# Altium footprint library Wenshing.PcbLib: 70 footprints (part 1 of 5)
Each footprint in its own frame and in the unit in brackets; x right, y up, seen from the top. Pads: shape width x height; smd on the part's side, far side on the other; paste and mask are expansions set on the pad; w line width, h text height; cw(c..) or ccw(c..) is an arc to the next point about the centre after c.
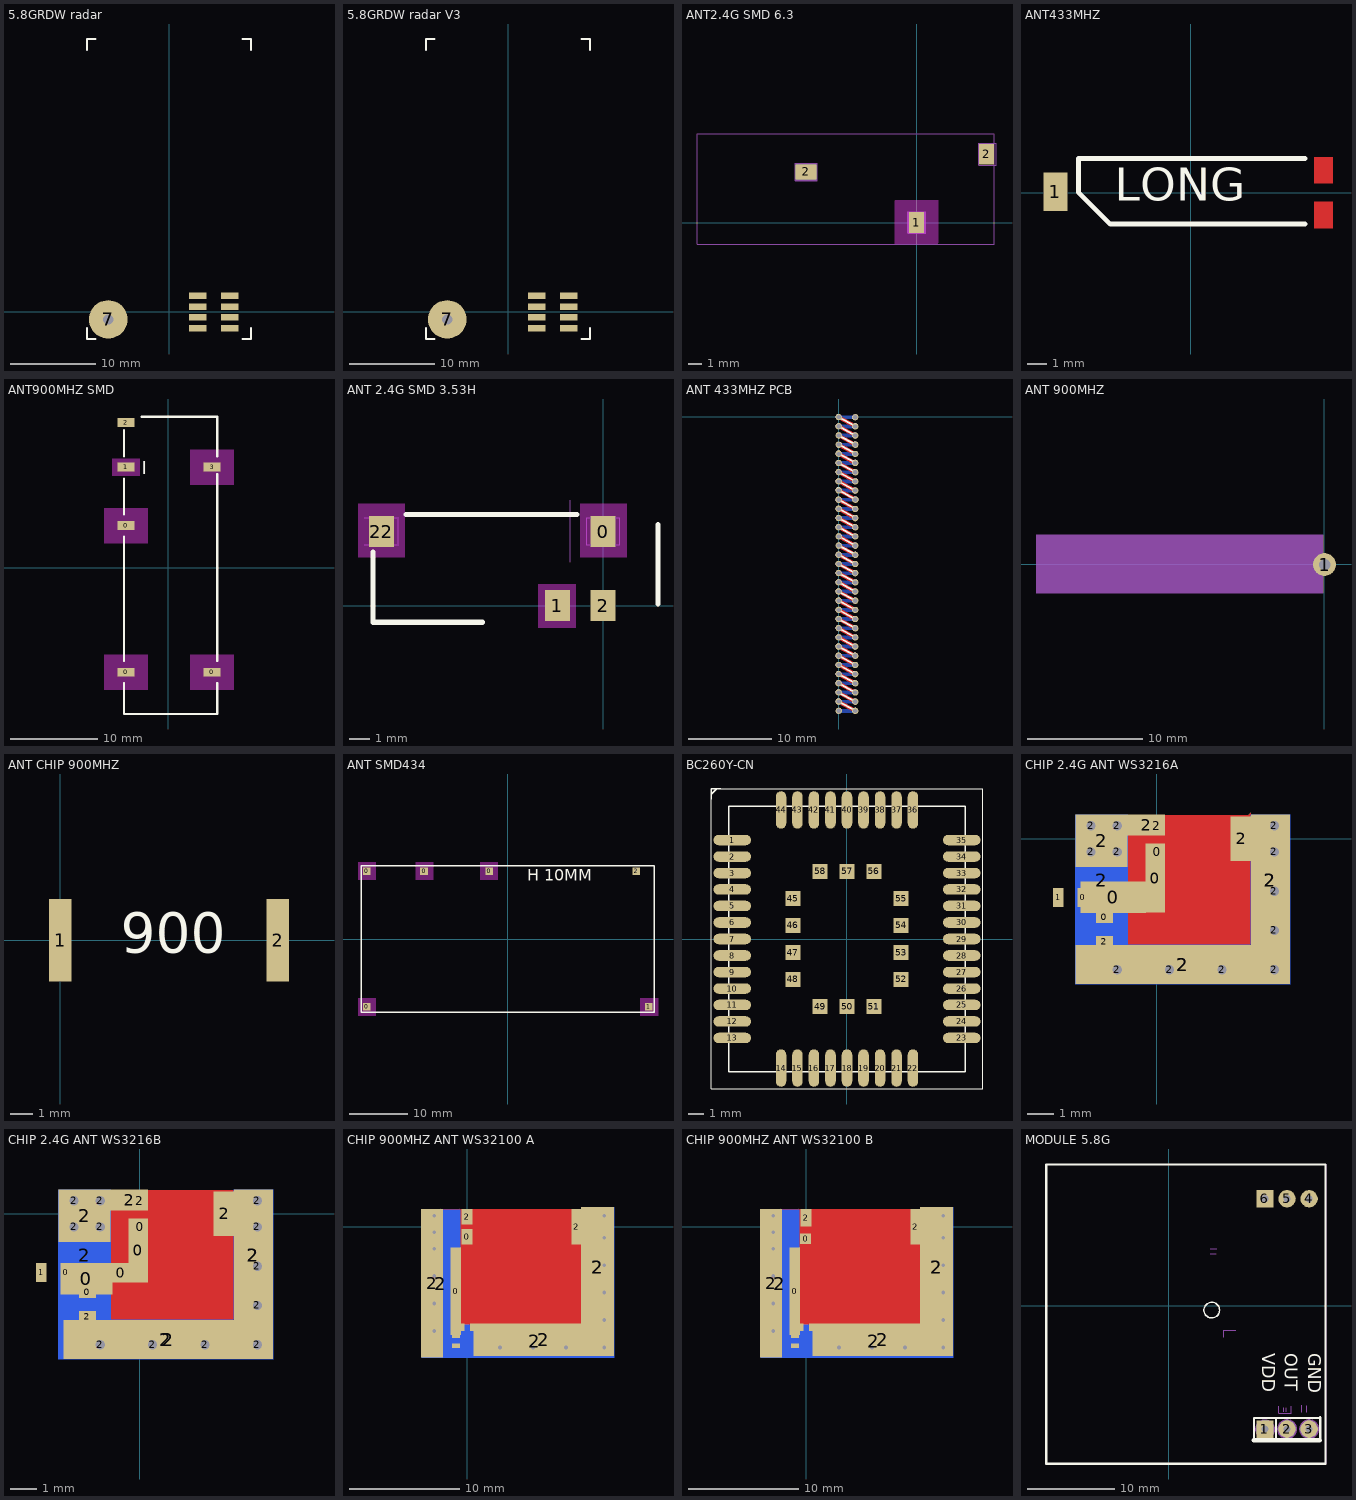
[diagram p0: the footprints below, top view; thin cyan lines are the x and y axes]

## 5.8GRDW radar [mm] "radar 5.8G"
pads (9):
  rect 2.05x0.76 smd: 1(7.109,1.905) 2(3.359,1.905) 3(7.109,0.635) 4(3.359,0.635) 5(7.109,-0.635) 6(3.359,-0.635) 7(7.109,-1.905) 8(3.359,-1.905)
  round 4.5 / inner round 4.5 / far side round 2 hole 1.2: 7(-7.109,-0.871)
Top Layer:
  lines w0.305: -8.587,0.607 ccw(c-7.109,0.607) -7.109,-0.871
Top Overlay:
  lines w0.254: -9.591,-1.887 -9.591,-3.157 -8.575,-3.157 ; -9.591,30.625 -9.591,31.895 -8.575,31.895 ; 8.57,-3.157 9.586,-3.157 9.586,-1.887 ; 8.57,31.895 9.586,31.895 9.586,30.625
Bottom Overlay:
  circle w0.305: c-7.109,-0.871 r2.032
3D body "實驗電源 .step": height 21.53, standoff -21.97, extent -30.585,-22.979 29.921,19.48
3D body: height 3, standoff 0, extent -8.759,-2.521 -5.459,0.779

## 5.8GRDW radar V3 [mm] "radar 5.8G"
pads (9):
  rect 2.05x0.76 smd: 1(7.109,1.905) 2(3.359,1.905) 3(7.109,0.635) 4(3.359,0.635) 5(7.109,-0.635) 6(3.359,-0.635) 7(7.109,-1.905) 8(3.359,-1.905)
  round 4.5 / inner round 4.5 / far side round 2 hole 1.2: 7(-7.109,-0.871)
Top Layer:
  lines w0.305: -8.587,0.607 ccw(c-7.109,0.607) -7.109,-0.871
Top Overlay:
  lines w0.254: -9.591,-1.887 -9.591,-3.157 -8.575,-3.157 ; -9.591,30.625 -9.591,31.895 -8.575,31.895 ; 8.57,-3.157 9.586,-3.157 9.586,-1.887 ; 8.57,31.895 9.586,31.895 9.586,30.625
Bottom Overlay:
  circle w0.305: c-7.109,-0.871 r2.032
3D body "TRW-RADAR 5.8G RT v3.step": height -1.8, standoff -5.66, extent -9.852,-3.195 9.754,33.421
3D body: height 3, standoff 0, extent -8.759,-2.521 -5.459,0.779

## ANT2.4G SMD 6.3 [mil] "ANT 2.4GHZ 6.3X21.8mm"
pads (3):
  rect 43.31x60 smd: 1(-1,0) 2(201,197)
  rect 60x43.31 smd: 2(-320,146)
Keep-Out Layer:
  region: -64,63 -63,64 62,64 62,-58 58,-62 -64,-62
Mechanical 1:
  region: -288.22,120.29 -351.22,120.29 -351.22,171.47 -288.22,171.47
  region: 24.77,-31.28 -26.41,-31.28 -26.41,31.71 24.77,31.71
  lines w0.39: -634.68,-50.97 -634.68,161.63 ; -622.87,-62.78 -193.74,-62.78 ; -59.88,-62.78 58.23,-62.78 ; 196.03,224.62 211.78,224.62 ; 223.59,-11.6 223.59,173.44 223.59,212.81 ; -634.68,-62.78 -634.68,256.12 223.59,256.12 223.59,-62.78 -634.68,-62.78 ; -351.22,120.29 -288.22,120.29 -288.22,171.47 -351.22,171.47 -351.22,120.29 ; -26.41,-31.28 24.77,-31.28 24.77,31.71 -26.41,31.71 -26.41,-31.28 ; 178.31,165.57 229.49,165.57 229.49,228.56 178.31,228.56 178.31,165.57
  text "GND" at -426.17,153.85 h19.68
  text "GND" at 105.59,204.89 h19.68
  text "RF FEED" at 44.35,8.12 h19.68
Mechanical 3:
  lines w0.39: -351.22,138.01 -351.22,153.76 ; -8.7,31.71 7.05,31.71

## ANT433MHZ [mil] "400MHZ -900MHZ   通用"
height 23.62
pads (1):
  rect 50x80 smd: 1(-280,2)
Top Layer:
  rectangle: 254.92,18.48 294.29,73.6
  rectangle: 254.92,-73.69 294.29,-18.57
Top Overlay:
  lines w10: 236.22,-64.96 135.58,-64.96 -65.7,-64.96 -166.34,-64.96 -232.28,0.98 -232.28,70.87 236.22,70.87
  text "LONG" at -157.48,-39.37 h118.11
Top Solder:
  rectangle: 250.98,-78.61 300.2,-14.64
  rectangle: 250.98,14.54 299.21,78.52
  rectangle: -225,-85 220,100
3D body: height 7.87, standoff 0, extent 148.5,-62 224.43,55.68
3D body: height 7.87, standoff 0, extent 90.5,-59 166.43,58.68
3D body: height 7.87, standoff 0, extent 31.5,-60 107.43,57.68
3D body: height 7.87, standoff 0, extent -28.5,-58 47.43,59.68
3D body: height 7.87, standoff 0, extent -73.5,-58 2.43,59.68
3D body: height 7.87, standoff 0, extent -148.5,-56 -72.57,61.68
3D body: height 7.87, standoff 0, extent -206.5,-58 -130.57,59.68
3D body: height 7.87, standoff 0, extent -262.5,-58 -186.57,59.68
3D body: height 51.18, standoff 47.24, extent -201.22,-58 -157,60.93
3D body: height 51.18, standoff 47.24, extent 209,-59.06 253.22,59.88
3D body: height 51.18, standoff 47.24, extent 149.95,-59.06 194.17,59.88
3D body: height 51.18, standoff 47.24, extent 90.89,-59.06 135.11,59.88
3D body: height 51.18, standoff 47.24, extent 31.84,-59.06 76.06,59.88
3D body: height 51.18, standoff 47.24, extent -27.22,-59.06 17,59.88
3D body: height 51.18, standoff 47.24, extent -86.27,-59.06 -42.06,59.88
3D body: height 51.18, standoff 47.24, extent -145.33,-59.06 -101.11,59.88
3D body: height 51.18, standoff 47.24, extent -201.22,-58 -157,60.93
3D body: height 51.18, standoff 0, extent 256,-58 297,60
3D body: height 51.18, standoff 0, extent -288,-58 -247,60
3D body: height 47.24, standoff 0, extent -246,-58.07 255,60.04

## ANT900MHZ SMD [mm]
height 0.6
pads (6):
  rect 1.95x1 smd: 0(-4.855,-12) 0(-4.855,4.8) 0(4.985,-12) 1(-4.855,11.5) 2(-4.855,16.6) 3(5.005,11.5)
Top Overlay:
  lines w0.254: -5.08,-13.208 -5.08,-16.764 5.588,-16.764 5.588,-13.208 ; -5.08,-10.668 -5.08,3.556 ; -5.08,6.096 -5.08,10.16 ; -5.08,12.7 -5.08,15.748 ; -3.048,17.272 5.588,17.272 5.588,12.7 ; 5.588,-10.668 5.588,10.668
  text "I" at -3.048,10.668 h1.52
Keep-Out Layer:
  pour cut-out: -2.35,2.775 -2.35,6.775 -7.35,6.775 -7.35,2.775
  pour cut-out: -3.275,10.525 -3.275,12.475 -6.4,12.475 -6.4,10.525
  pour cut-out: 7.5,-14 7.5,-10 2.5,-10 2.5,-14
  pour cut-out: -2.35,-13.975 -2.35,-9.975 -7.35,-9.975 -7.35,-13.975
  pour cut-out: 7.5,9.5 7.5,13.5 2.5,13.5 2.5,9.5
3D body "ANT 900MHZ ON PCBA (2).stp": height 5, standoff 0.1, extent -5.7,-17.025 5.9,17.025

## ANT 2.4G SMD 3.53H [mm] "ANT 2.4GHZ"
pads (4):
  rect 1.2x1.5 smd: 0(0,3.57) 1(-2.2,0) 2(0,0) 22(-10.7,3.57)
Top Overlay:
  lines w0.254: -11.1,2.575 -11.1,-0.8 -5.825,-0.8 ; -9.5,4.4 -1.275,4.4 ; 2.65,0.075 2.65,3.9
Keep-Out Layer:
  region: -1.325,1.025 -1.325,-1.075 -3.125,-1.075 -3.125,1.025
  region: -11.825,4.925 -9.575,4.925 -9.575,2.325 -11.825,2.325
  region: -1.1,4.925 1.15,4.925 1.15,2.325 -1.1,2.325
Mechanical 1:
  lines w0.01: -11.495,2.941 -9.895,2.941 -9.895,4.241 -11.495,4.241 ; -1.595,2.091 -1.595,5.091 ; -0.795,2.941 0.805,2.941 0.805,4.241 -0.795,4.241 -0.795,2.941
  text "GND" at 0.772,0.258 h0.5
  text "RF FEED" at -4.308,2.37 h0.5
Mechanical 3:
  lines w0.01: -9.895,3.391 -9.895,3.791 ; 0.805,3.391 0.805,3.791
3D body "ant 2.4g.STEP": height 3.56, standoff 0.04, extent -11.066,-0.784 2.684,4.445

## ANT 433MHZ PCB [mm]
pads (66):
  round 0.75 hole 0.5 mask+0.102: 1(0.012,-35.217) 1(0.012,-34.117) 1(0.012,-33.017) 1(0.012,-31.917) 1(0.012,-30.817) 1(0.012,-29.717) 1(0.012,-28.617) 1(0.012,-27.517) 1(0.012,-26.417) 1(0.012,-25.317) 1(0.012,-24.217) 1(0.012,-23.117) 1(0.012,-22.017) 1(0.012,-20.917) 1(0.012,-19.817) 1(0.012,-18.717) 1(0.012,-17.617) 1(0.012,-16.517) 1(0.012,-15.417) 1(0.012,-14.317) 1(0.012,-13.217) 1(0.012,-12.117) 1(0.012,-11.017) 1(0.012,-9.917) 1(0.012,-8.817) 1(0.012,-7.717) 1(0.012,-6.617) 1(0.012,-5.517) 1(0.012,-4.417) 1(0.012,-3.317) 1(0.012,-2.217) 1(0.012,-1.117) 1(0.012,-0.017) 1(2,-35.225) 1(2,-34.125) 1(2,-33.025) 1(2,-31.925) 1(2,-30.825) 1(2,-29.725) 1(2,-28.625) 1(2,-27.525) 1(2,-26.425) 1(2,-25.325) 1(2,-24.225) 1(2,-23.125) 1(2,-22.025) 1(2,-20.925) 1(2,-19.825) 1(2,-18.725) 1(2,-17.625) 1(2,-16.525) 1(2,-15.425) 1(2,-14.325) 1(2,-13.225) 1(2,-12.125) 1(2,-11.025) 1(2,-9.925) 1(2,-8.825) 1(2,-7.725) 1(2,-6.625) 1(2,-5.525) 1(2,-4.425) 1(2,-3.325) 1(2,-2.225) 1(2,-1.125) 1(2,-0.025)
Top Layer:
  lines w0.457: 0.012,-34.117 2,-35.225 ; 0.012,-33.017 2,-34.125 ; 0.012,-31.917 2,-33.025 ; 0.012,-30.817 2,-31.925 ; 0.012,-29.717 2,-30.825 ; 0.012,-28.617 2,-29.725 ; 0.012,-27.517 2,-28.625 ; 0.012,-26.417 2,-27.525 ; 0.012,-25.317 2,-26.425 ; 0.012,-24.217 2,-25.325 ; 0.012,-23.117 2,-24.225 ; 0.012,-22.017 2,-23.125 ; 0.012,-20.917 2,-22.025 ; 0.012,-19.817 2,-20.925 ; 0.012,-18.717 2,-19.825 ; 0.012,-17.617 2,-18.725 ; 0.012,-16.517 2,-17.625 ; 0.012,-15.417 2,-16.525 ; 0.012,-14.317 2,-15.425 ; 0.012,-13.217 2,-14.325 ; 0.012,-12.117 2,-13.225 ; 0.012,-11.017 2,-12.125 ; 0.012,-9.917 2,-11.025 ; 0.012,-7.717 2,-8.825 ; 0.012,-6.617 2,-7.725 ; 0.012,-5.517 2,-6.625 ; 0.012,-4.417 2,-5.525 ; 0.012,-3.317 2,-4.425 ; 0.012,-2.217 2,-3.325 ; 0.012,-1.117 2,-2.225 ; 0.012,-0.017 2,-1.125 ; 0.031,-8.759 2.019,-9.868
Bottom Layer:
  lines w0.457: 0.012,-35.225 2,-35.225 ; 0.012,-34.125 2,-34.125 ; 0.012,-33.025 2,-33.025 ; 0.012,-31.925 2,-31.925 ; 0.012,-30.825 2,-30.825 ; 0.012,-29.725 2,-29.725 ; 0.012,-28.625 2,-28.625 ; 0.012,-27.525 2,-27.525 ; 0.012,-26.425 2,-26.425 ; 0.012,-25.325 2,-25.325 ; 0.012,-24.225 2,-24.225 ; 0.012,-23.125 2,-23.125 ; 0.012,-22.025 2,-22.025 ; 0.012,-20.925 2,-20.925 ; 0.012,-19.825 2,-19.825 ; 0.012,-18.725 2,-18.725 ; 0.012,-17.625 2,-17.625 ; 0.012,-16.525 2,-16.525 ; 0.012,-15.425 2,-15.425 ; 0.012,-14.325 2,-14.325 ; 0.012,-13.225 2,-13.225 ; 0.012,-12.125 2,-12.125 ; 0.012,-11.025 2,-11.025 ; 0.012,-9.925 2,-9.925 ; 0.012,-8.825 2,-8.825 ; 0.012,-7.725 2,-7.725 ; 0.012,-6.625 2,-6.625 ; 0.012,-5.525 2,-5.525 ; 0.012,-4.425 2,-4.425 ; 0.012,-3.325 2,-3.325 ; 0.012,-2.225 2,-2.225 ; 0.012,-1.125 2,-1.125 ; 0.012,-0.025 2,-0.025
Top Overlay:
  circle w0.3: c0,0 r0.2
  circle w0.3: c1.975,-0.025 r0.2
  circle w0.3: c1.975,-1.1 r0.2
  circle w0.3: c0,-1.1 r0.2
  circle w0.3: c1.975,-2.2 r0.2
  circle w0.3: c0.025,-2.2 r0.2
  circle w0.3: c1.975,-4.4 r0.2
  circle w0.3: c0,-4.375 r0.2
  circle w0.3: c0.038,-3.321 r0.2
  circle w0.3: c2,-3.3 r0.2
  circle w0.3: c1.975,-5.475 r0.2
  circle w0.3: c0,-5.5 r0.2
  circle w0.3: c1.975,-6.6 r0.2
  circle w0.3: c0,-6.6 r0.2
  circle w0.3: c1.975,-7.7 r0.2
  circle w0.3: c0,-7.7 r0.2
  circle w0.3: c1.975,-8.8 r0.2
  circle w0.3: c0,-8.75 r0.2
  circle w0.3: c0,-9.9 r0.2
  circle w0.3: c2.024,-9.877 r0.2
  circle w0.3: c1.975,-11 r0.2
  circle w0.3: c0,-10.975 r0.2
  circle w0.3: c1.975,-12.075 r0.2
  circle w0.3: c0,-12.1 r0.2
  circle w0.3: c1.975,-13.2 r0.2
  circle w0.3: c0,-13.2 r0.2
  circle w0.3: c1.975,-14.3 r0.2
  circle w0.3: c0.05,-14.3 r0.2
  circle w0.3: c1.975,-15.4 r0.2
  circle w0.3: c0.025,-15.4 r0.2
  circle w0.3: c2,-16.5 r0.2
  circle w0.3: c0,-16.5 r0.2
  circle w0.3: c1.975,-17.6 r0.2
  circle w0.3: c0,-17.6 r0.2
  circle w0.3: c1.975,-18.7 r0.2
  circle w0.3: c0,-18.7 r0.2
  circle w0.3: c1.975,-19.8 r0.2
  circle w0.3: c0,-19.8 r0.2
  circle w0.3: c1.975,-20.9 r0.2
  circle w0.3: c0,-20.9 r0.2
  circle w0.3: c1.975,-22 r0.2
  circle w0.3: c0,-22 r0.2
  circle w0.3: c1.975,-23.1 r0.2
  circle w0.3: c0,-23.1 r0.2
  circle w0.3: c1.975,-24.2 r0.2
  circle w0.3: c0,-24.2 r0.2
  circle w0.3: c1.975,-25.3 r0.2
  circle w0.3: c0,-25.3 r0.2
  circle w0.3: c1.975,-26.4 r0.2
  circle w0.3: c0,-26.4 r0.2
  circle w0.3: c1.975,-27.5 r0.2
  circle w0.3: c0,-27.5 r0.2
  circle w0.3: c1.975,-28.6 r0.2
  circle w0.3: c0,-28.6 r0.2
  circle w0.3: c1.975,-29.7 r0.2
  circle w0.3: c0,-29.7 r0.2
  circle w0.3: c1.975,-30.8 r0.2
  circle w0.3: c0,-30.8 r0.2
  circle w0.3: c1.975,-31.9 r0.2
  circle w0.3: c0,-31.9 r0.2
  circle w0.3: c1.975,-33 r0.2
  circle w0.3: c0,-33 r0.2
  circle w0.3: c1.975,-34.1 r0.2
  circle w0.3: c0,-34.1 r0.2
  circle w0.3: c1.975,-35.2 r0.2
  circle w0.3: c0.025,-35.204 r0.2
  lines w0.254: 0,-34.1 1.975,-35.2 ; 0,-33 1.975,-34.1 ; 0,-31.9 1.975,-33 ; 0,-30.8 1.975,-31.9 ; 0,-29.7 1.975,-30.8 ; 0,-28.6 1.975,-29.7 ; 0,-27.5 1.975,-28.6 ; 0,-26.4 1.975,-27.5 ; 0,-25.3 1.975,-26.4 ; 0,-24.2 1.975,-25.3 ; 0,-23.1 1.975,-24.2 ; 0,-22 1.975,-23.1 ; 0,-20.9 1.975,-22 ; 0,-19.8 1.975,-20.9 ; 0,-18.7 1.975,-19.8 ; 0,-17.6 1.975,-18.7 ; 0,-16.5 1.975,-17.6 ; 0,-13.2 1.975,-14.3 ; 0,-12.1 1.975,-13.2 ; 0,-10.975 1.975,-12.075 ; 0,-9.9 1.975,-11 ; 0,-8.75 2.024,-9.877 ; 0,-7.7 1.975,-8.8 ; 0,-6.6 1.975,-7.7 ; 0,-5.5 1.975,-6.6 ; 0,-4.375 1.975,-5.475 ; 0,-1.1 1.975,-2.2 ; 0,0 1.975,-1.1 ; 0.025,-15.4 2,-16.5 ; 0.025,-2.2 2,-3.3 ; 0.038,-3.321 1.975,-4.4 ; 0.05,-14.3 1.975,-15.4
Bottom Overlay:
  circle w0.3: c2.007,-0.025 r0.2
  circle w0.3: c0,0 r0.2
  circle w0.3: c2.007,-1.118 r0.2
  circle w0.3: c0,-1.118 r0.2
  circle w0.3: c2.007,-2.21 r0.2
  circle w0.3: c0,-2.21 r0.2
  circle w0.3: c2.007,-3.327 r0.2
  circle w0.3: c0,-3.327 r0.2
  circle w0.3: c2.007,-4.42 r0.2
  circle w0.3: c0,-4.42 r0.2
  circle w0.3: c2.007,-5.537 r0.2
  circle w0.3: c0,-5.512 r0.2
  circle w0.3: c2.007,-6.629 r0.2
  circle w0.3: c0,-6.629 r0.2
  circle w0.3: c2.007,-7.722 r0.2
  circle w0.3: c0,-7.722 r0.2
  circle w0.3: c2.007,-8.814 r0.2
  circle w0.3: c0,-8.814 r0.2
  circle w0.3: c2.007,-9.931 r0.2
  circle w0.3: c0,-9.931 r0.2
  circle w0.3: c2.007,-11.024 r0.2
  circle w0.3: c0,-10.998 r0.2
  circle w0.3: c2.007,-12.116 r0.2
  circle w0.3: c0,-12.116 r0.2
  circle w0.3: c2.007,-13.233 r0.2
  circle w0.3: c0,-13.208 r0.2
  circle w0.3: c2.007,-14.326 r0.2
  circle w0.3: c0,-14.326 r0.2
  circle w0.3: c2.007,-15.418 r0.2
  circle w0.3: c0.025,-15.418 r0.2
  circle w0.3: c2.007,-16.535 r0.2
  circle w0.3: c0.025,-16.51 r0.2
  circle w0.3: c2.007,-17.628 r0.2
  circle w0.3: c0.025,-17.602 r0.2
  circle w0.3: c2.007,-18.72 r0.2
  circle w0.3: c0,-18.72 r0.2
  circle w0.3: c2.007,-19.812 r0.2
  circle w0.3: c0,-19.812 r0.2
  circle w0.3: c2.007,-20.93 r0.2
  circle w0.3: c0,-20.93 r0.2
  circle w0.3: c2.007,-22.022 r0.2
  circle w0.3: c0,-22.022 r0.2
  circle w0.3: c1.981,-23.114 r0.2
  circle w0.3: c0,-23.114 r0.2
  circle w0.3: c2.007,-24.232 r0.2
  circle w0.3: c0,-24.206 r0.2
  circle w0.3: c2.007,-25.324 r0.2
  circle w0.3: c0,-25.298 r0.2
  circle w0.3: c2.007,-26.416 r0.2
  circle w0.3: c0,-26.416 r0.2
  circle w0.3: c2.007,-27.508 r0.2
  circle w0.3: c0,-27.508 r0.2
  circle w0.3: c2.007,-28.626 r0.2
  circle w0.3: c0,-28.6 r0.2
  circle w0.3: c2.007,-29.718 r0.2
  circle w0.3: c0,-29.718 r0.2
  circle w0.3: c2.007,-30.836 r0.2
  circle w0.3: c0,-30.81 r0.2
  circle w0.3: c2.007,-31.928 r0.2
  circle w0.3: c0,-31.928 r0.2
  circle w0.3: c2.007,-33.02 r0.2
  circle w0.3: c0,-33.02 r0.2
  circle w0.3: c0,-34.112 r0.2
  circle w0.3: c2.007,-34.138 r0.2
  circle w0.3: c2.007,-35.23 r0.2
  circle w0.3: c0,-35.204 r0.2
  lines w0.254: 0,-35.204 2.007,-35.23 ; 0,-34.112 2.007,-34.138 ; 0,-33.02 2.007,-33.045 ; 0,-31.928 2.007,-31.953 ; 0,-30.81 2.007,-30.836 ; 0,-29.718 2.007,-29.743 ; 0,-28.6 2.007,-28.626 ; 0,-27.508 2.007,-27.534 ; 0,-26.416 2.007,-26.441 ; 0,-25.298 2.007,-25.324 ; 0,-24.206 2.007,-24.232 ; 0,-23.114 2.007,-23.139 ; 0,-22.022 2.007,-22.047 ; 0,-20.93 2.007,-20.955 ; 0,-19.812 2.007,-19.837 ; 0,-18.72 2.007,-18.745 ; 0,-14.326 2.007,-14.351 ; 0,-13.208 2.007,-13.233 ; 0,-12.116 2.007,-12.141 ; 0,-10.998 2.007,-11.024 ; 0,-9.931 2.007,-9.957 ; 0,-8.814 2.007,-8.839 ; 0,-7.722 2.007,-7.747 ; 0,-6.629 2.007,-6.655 ; 0,-5.512 2.007,-5.537 ; 0,-4.42 2.007,-4.445 ; 0,-3.327 2.007,-3.353 ; 0,-2.21 2.007,-2.235 ; 0,-1.118 2.007,-1.143 ; 0,0 2.007,-0.025 ; 0.025,-17.602 2.032,-17.628 ; 0.025,-16.51 2.032,-16.535 ; 0.025,-15.418 2.032,-15.443

## ANT 900MHZ [mm]
pads (1):
  round 2 hole 1: 1(0.025,-0.05)
Mechanical 1:
  rectangle: -25.075,-2.55 -0.075,2.55

## ANT CHIP 900MHZ [mm] "900MHZ"
height 0.6
pads (2):
  rect 1x3.6 smd: 1(0,0) 2(9.5,0)
Top Overlay:
  text "900" at 2.642,-1.118 h3
Top Solder:
  rectangle: 0.914,-1.803 8.661,1.93
3D body: height 0.2, standoff 0, extent 7.912,-1.575 9.841,1.414
3D body: height 0.2, standoff 0, extent 6.388,-1.524 8.317,1.465
3D body: height 0.2, standoff 0, extent 5.245,-1.524 7.174,1.465
3D body: height 0.2, standoff 0, extent 3.34,-1.473 5.269,1.516
3D body: height 0.2, standoff 0, extent 1.867,-1.524 3.796,1.465
3D body: height 0.2, standoff 0, extent 0.445,-1.524 2.373,1.465
3D body: height 1.3, standoff 1.2, extent 2.001,-1.524 3.124,1.497
3D body: height 1.3, standoff 1.2, extent 7.921,-1.551 9.044,1.47
3D body: height 1.3, standoff 1.2, extent 6.421,-1.551 7.544,1.47
3D body: height 1.3, standoff 1.2, extent 4.921,-1.551 6.044,1.47
3D body: height 1.3, standoff 1.2, extent 3.421,-1.551 4.544,1.47
3D body: height 1.3, standoff 1.2, extent 2.001,-1.524 3.124,1.497
3D body: height 1.3, standoff 0, extent 9.004,-1.524 10.046,1.473
3D body: height 1.3, standoff 0, extent -0.203,-1.524 0.838,1.473
3D body: height 1.2, standoff 0, extent 0.864,-1.526 9.779,1.474

## ANT SMD434 [mm] "貼片銅天線 434MHZ"
height 10
pads (6):
  rect 1.3x1.3 smd: 0(-24.005,-11.57) 0(-24.005,11.57) 0(-14.255,11.57) 0(-3.155,11.57) 1(24.005,-11.57) 2(21.905,11.57)
Top Overlay:
  lines w0.254: -24.965,12.498 24.965,12.498 ; -24.965,12.5 -24.965,-12.47 24.965,-12.47 ; 24.971,-12.47 24.971,12.5
  text "H 10MM" at 3.331,9.907 h2
Keep-Out Layer:
  region: -4.7,10.1 -1.7,10.1 -1.7,13.1 -4.7,13.1
  region: -15.7,10.1 -12.7,10.1 -12.7,13.1 -15.7,13.1
  region: -25.5,10.1 -22.5,10.1 -22.5,13.1 -25.5,13.1
  region: 22.6,-13.1 25.6,-13.1 25.6,-10.1 22.6,-10.1
  region: -25.5,-13.1 -22.5,-13.1 -22.5,-10.1 -25.5,-10.1
3D body "天線smd 438mhz.stp": height 10, standoff 0, extent -25,-12.617 25,12.383

## BC260Y-CN [mm]
pads (58):
  oval 2.5x0.7 smd mask+0.05: 1(-7.65,6.6) 2(-7.65,5.5) 3(-7.65,4.4) 4(-7.65,3.3) 5(-7.65,2.2) 6(-7.65,1.1) 7(-7.65,0) 8(-7.65,-1.1) 9(-7.65,-2.2) 10(-7.65,-3.3) 11(-7.65,-4.4) 12(-7.65,-5.5) 13(-7.65,-6.6) 23(7.65,-6.6) 24(7.65,-5.5) 25(7.65,-4.4) 26(7.65,-3.3) 27(7.65,-2.2) 28(7.65,-1.1) 29(7.65,0) 30(7.65,1.1) 31(7.65,2.2) 32(7.65,3.3) 33(7.65,4.4) 34(7.65,5.5) 35(7.65,6.6)
  oval 0.7x2.5 smd mask+0.05: 14(-4.4,-8.6) 15(-3.3,-8.6) 16(-2.2,-8.6) 17(-1.1,-8.6) 18(0,-8.6) 19(1.1,-8.6) 20(2.2,-8.6) 21(3.3,-8.6) 22(4.4,-8.6) 36(4.4,8.6) 37(3.3,8.6) 38(2.2,8.6) 39(1.1,8.6) 40(0,8.6) 41(-1.1,8.6) 42(-2.2,8.6) 43(-3.3,8.6) 44(-4.4,8.6)
  rect 1x1 smd mask+0.05: 45(-3.6,2.7) 46(-3.6,0.9) 47(-3.6,-0.9) 48(-3.6,-2.7) 49(-1.8,-4.5) 50(0,-4.5) 51(1.8,-4.5) 52(3.6,-2.7) 53(3.6,-0.9) 54(3.6,0.9) 55(3.6,2.7) 56(1.8,4.5) 57(0,4.5) 58(-1.8,4.5)
Top Overlay:
  lines w0.01: -9.05,-10 -9.05,10 9.05,10 9.05,-10 -9.05,-10
  lines w0.1: -9.05,9.325 -9.05,10 -8.4,10 ; -9.05,9.65 -8.725,9.975 ; -7.9,-8.85 -7.9,8.85 7.9,8.85 7.9,-8.85 -7.9,-8.85
3D body "Quectel_BC260Y-CN_3D_Dimensions.stp": height 2, standoff 0, extent -7.9,-8.85 7.9,8.85

## CHIP 2.4G ANT WS3216A [mm] "Wenshing 2.4g 3216"
pads (28):
  rect 0.406x0.711 smd: 0(-2.812,-2.239) 1(-3.752,-2.239)
  rect 0.65x0.45 smd mask+0.05: 0(-1.987,-2.999) 2(-1.987,-3.938)
  rect 2.5x1.2 smd: 0(-1.65,-2.225)
  rect 0.75x2.63 smd: 0(-0.05,-1.5)
  rect 0.6x0.6 smd: 0(0.025,-0.5) 2(0,0.5)
  round 0.5 hole 0.35: 2(-2.5,-0.5) 2(-2.5,0.5) 2(-1.5,-5) 2(-1.5,-0.5) 2(-1.5,0.5) 2(0.5,-5) 2(2.5,-5) 2(4.5,-5) 2(4.5,-3.5) 2(4.5,-2) 2(4.5,-0.5) 2(4.5,0.5)
  rect 2x5 smd far side: 2(-2.1,-1.575)
  rect 2x2 smd: 2(-2.1,-0.075)
  rect 1.45x0.8 smd: 2(-0.4,0.525)
  rect 8.2x1.5 smd: 2(1,-4.8)
  rect 8.2x1.5 smd far side: 2(1,-4.8)
  rect 0.8x1.7 smd: 2(3.225,0)
  rect 1.5x5 smd: 2(4.35,-1.575)
  rect 1.5x5 smd far side: 2(4.35,-1.575)
Top Layer:
  pour cut-out: -1.1,0.9 3.5,0.9 3.6,1 3.6,-4.1 -0.9,-4.1 -1.1,-4.1
Bottom Layer:
  pour cut-out: -1.1,0.9 3.5,0.9 3.6,1 3.6,-4.1 -0.9,-4.1 -1.1,-4.1
Top Overlay:
  lines w0.1: -2.215,-3.57 -1.758,-3.57 ; -2.215,-3.367 -1.758,-3.367
Top Solder:
  rectangle: 0.85,-0.9 2.375,0.9
  rectangle: 0.5,-3.9 3.5,-1.1
Bottom Solder:
  rectangle: -1.1,-4 3.625,0.925
Mechanical 15:
  lines w0.025: -2.387,-4.169 -1.587,-4.169 ; -2.387,-2.769 -1.587,-2.769
3D body "CAP0402C.STEP": height 0.36, standoff 0, extent -2.227,-3.969 -1.697,-2.969
3D body "INDUCTOR0402h025.STEP": height 0.25, standoff 0, extent -3.782,-2.489 -2.782,-1.989

## CHIP 2.4G ANT WS3216B [mm] "Wenshing 2.4g 3216"
pads (29):
  rect 0.406x0.711 smd: 0(-2.812,-2.239) 1(-3.752,-2.239)
  rect 2x1.2 smd: 0(-2.025,-2.475)
  rect 0.65x0.45 smd mask+0.05: 0(-1.987,-2.999) 2(-1.987,-3.938)
  rect 0.7x0.75 smd: 0(-0.725,-2.25)
  rect 0.75x2.45 smd: 0(-0.05,-1.4)
  rect 0.6x0.6 smd: 0(0.025,-0.5) 2(0,0.5)
  round 0.5 hole 0.35: 2(-2.5,-0.5) 2(-2.5,0.5) 2(-1.5,-5) 2(-1.5,-0.5) 2(-1.5,0.5) 2(0.5,-5) 2(2.5,-5) 2(4.5,-5) 2(4.5,-3.5) 2(4.5,-2) 2(4.5,-0.5) 2(4.5,0.5)
  rect 2x5 smd far side: 2(-2.1,-1.575)
  rect 2x2 smd: 2(-2.1,-0.075)
  rect 1.45x0.8 smd: 2(-0.4,0.525)
  rect 8.2x1.5 smd far side: 2(1,-4.8)
  rect 8x1.5 smd: 2(1.1,-4.8)
  rect 0.8x1.7 smd: 2(3.225,0)
  rect 1.5x5 smd: 2(4.35,-1.575)
  rect 1.5x5 smd far side: 2(4.35,-1.575)
Top Layer:
  pour cut-out: -1.2,0.9 3.9,0.9 3.9,-4.1 -1.2,-4.1
Bottom Layer:
  pour cut-out: -1.2,0.9 3.9,0.9 3.9,-4.1 -1.2,-4.1
Top Overlay:
  lines w0.1: -2.215,-3.57 -1.758,-3.57 ; -2.215,-3.367 -1.758,-3.367
Top Solder:
  rectangle: 0.5,-3.9 3.5,-1.1
  rectangle: 0.85,-0.9 2.375,0.9
Bottom Solder:
  rectangle: -1.1,-4 3.625,0.925
Mechanical 15:
  lines w0.025: -2.387,-4.169 -1.587,-4.169 ; -2.387,-2.769 -1.587,-2.769
3D body "INDUCTOR0402h025.STEP": height 0.25, standoff 0, extent -3.782,-2.489 -2.782,-1.989
3D body "CAP0402C.STEP": height 0.36, standoff 0, extent -2.227,-3.969 -1.697,-2.969

## CHIP 900MHZ ANT WS32100 A [mm] "Wenshing 900MHZ ANT 3.2X10mm"
pads (29):
  rect 0.94x8 smd: 0(-1.05,-5.875)
  rect 0.711x0.406 smd: 0(-1.011,-9.912) 1(-1.011,-10.852)
  rect 0.45x0.65 smd mask+0.05: 0(-0.451,-9.162) 2(0.488,-9.162)
  rect 1x1.4 smd: 0(0,-0.9) 2(0,0.9)
  rect 2x13.5 smd: 2(-3.2,-5.15)
  round 0.5 hole 0.35: 2(-3,-9.5) 2(-3,-7) 2(-3,-4.5) 2(-3,-2) 2(-3,-0.5) 2(-3,1) 2(3,-11) 2(6,-11) 2(9,-11) 2(12.5,-11) 2(12.5,-8.5) 2(12.5,-6) 2(12.5,-3.5) 2(12.5,-1) 2(12.5,1)
  rect 3.5x13.5 smd far side: 2(-2.4,-5.2)
  rect 14.5x3 smd far side: 2(6.15,-10.45)
  rect 12.8x3 smd: 2(7,-10.3)
  rect 1x3.2 smd: 2(10,0)
  rect 3x11 smd: 2(11.9,-3.7)
  rect 3x11 smd far side: 2(11.9,-3.7)
Top Layer:
  rectangle: -3.3,0.4 0.3,1.6
  pour cut-out: -2.4,1.629 -2.4,-10.8 9.1,-10.8 10.4,-9.5 10.4,1.6
  lines w0.94: -1.05,-2.116 cw(c-0.05,-2.1) -0.05,-1.1
  lines w1.2: -2.95,-2.045 cw(c-0.1,-2) -0.489,0.823
Bottom Layer:
  pour cut-out: -0.7,1.625 -0.575,1.5 -0.575,-8.925 10.4,-8.925 10.4,1.6
Top Overlay:
  lines w0.1: -0.083,-9.39 -0.083,-8.933 ; 0.12,-9.39 0.12,-8.933
Top Solder:
  rectangle: -0.5,-8.775 10.3,-2
  rectangle: 1.2,-2.1 8.9,1.7
Bottom Solder:
  rectangle: -0.6,-8.8 10.4,1.7
Mechanical 15:
  lines w0.025: -0.681,-9.562 -0.681,-8.762 ; 0.719,-9.562 0.719,-8.762
3D body: height 0.5, standoff 0, extent 9.55,-1.612 10.088,1.575
3D body: height 0.5, standoff 0, extent -0.025,-1.587 0.513,1.6
3D body: height 0.4, standoff 0, extent -0.025,-1.6 10,1.6
3D body "INDUCTOR0402h025.STEP": height 0.25, standoff 0, extent -1.261,-10.882 -0.761,-9.882
3D body "CAP0402C.STEP": height 0.36, standoff 0, extent -0.481,-9.402 0.519,-8.872

## CHIP 900MHZ ANT WS32100 B [mm] "Wenshing 900MHZ ANT 3.2X10mm"
pads (29):
  rect 0.94x8 smd: 0(-1.05,-5.875)
  rect 0.711x0.406 smd: 0(-1.011,-9.912) 1(-1.011,-10.852)
  rect 0.45x0.65 smd mask+0.05: 0(-0.451,-9.162) 2(0.488,-9.162)
  rect 1x0.94 smd: 0(-0.05,-1.1)
  rect 2x13.5 smd: 2(-3.2,-5.15)
  round 0.5 hole 0.35: 2(-3,-9.5) 2(-3,-7) 2(-3,-4.5) 2(-3,-2) 2(-3,-0.5) 2(-3,1) 2(3,-11) 2(6,-11) 2(9,-11) 2(12.5,-11) 2(12.5,-8.5) 2(12.5,-6) 2(12.5,-3.5) 2(12.5,-1) 2(12.5,1)
  rect 3.5x13.5 smd far side: 2(-2.4,-5.2)
  rect 1x1.6 smd: 2(0,0.825)
  rect 14.5x3 smd far side: 2(6.15,-10.45)
  rect 12.8x3 smd: 2(7,-10.3)
  rect 1x3.2 smd: 2(10,0)
  rect 3x11 smd: 2(11.9,-3.7)
  rect 3x11 smd far side: 2(11.9,-3.7)
Top Layer:
  rectangle: -3.3,0.4 0.3,1.6
  pour cut-out: -2.3,1.629 -2.3,-10.8 8.525,-10.8 10.4,-8.925 10.4,1.6
  lines w0.94: -1.05,-2.116 cw(c-0.05,-2.1) -0.05,-1.1
  lines w1.6: -2.95,-2.045 cw(c-0.1,-2) -0.489,0.823
Bottom Layer:
  pour cut-out: -0.7,1.625 -0.575,1.5 -0.575,-8.975 10.35,-8.975 10.4,-8.925 10.4,1.6
Top Overlay:
  lines w0.1: -0.083,-9.39 -0.083,-8.933 ; 0.12,-9.39 0.12,-8.933
Top Solder:
  rectangle: 1.2,-2.3 8.9,1.7
  rectangle: -0.5,-8.775 10.4,-2.2
Bottom Solder:
  rectangle: -0.5,-8.775 10.4,1.7
Mechanical 15:
  lines w0.025: -0.681,-9.562 -0.681,-8.762 ; 0.719,-9.562 0.719,-8.762
3D body: height 0.5, standoff 0, extent 9.55,-1.612 10.088,1.575
3D body: height 0.5, standoff 0, extent -0.025,-1.587 0.513,1.6
3D body: height 0.4, standoff 0, extent -0.025,-1.6 10,1.6
3D body "INDUCTOR0402h025.STEP": height 0.25, standoff 0, extent -1.261,-10.882 -0.761,-9.882
3D body "CAP0402C.STEP": height 0.36, standoff 0, extent -0.481,-9.402 0.519,-8.872

## MODULE 5.8G [mm]
pads (6):
  rect 2x2 hole 0.813: 1(11.057,-14.189) 6(11.057,12.311)
  round 2 hole 0.813: 2(13.597,-14.189) 3(16.137,-14.189) 4(16.137,12.311) 5(13.597,12.311)
Top Overlay:
  circle w0.152: c4.925,-0.5 r0.903
  lines w0.051: 17.357,-15.454 17.458,-15.352
  lines w0.254: 12.327,-15.459 12.327,-12.919 ; 17.382,-12.787 17.458,-12.863 17.458,-15.352 ; -14.097,-18.161 18.034,-18.161 18.034,16.256 -14.097,16.256 -14.097,-18.161 ; 9.787,-15.459 9.787,-12.919 17.407,-12.919 17.407,-15.459 9.787,-15.459
  lines w0.508: 9.75,-15.454 17.357,-15.454
  text "GND" at 15.525,-5.475 h2.5
  text "VDD" at 10.225,-5.45 h2.5
  text "OUT" at 12.8,-5.475 h2.5
Mechanical 1:
  lines w0.127: -14.153,-18.127 -14.153,16.311 ; -14.153,-17.939 -14.153,16.311 ; -13.911,-18.197 9.589,-18.197 9.597,-18.189 18.097,-18.189 ; -13.903,-18.189 18.097,-18.189 ; -14.153,16.311 18.097,16.311 ; -14.153,16.311 18.097,16.311 ; 18.097,-18.189 18.097,16.311 ; 18.097,-18.189 18.097,16.311
Sheet:
  circle w0.254: c11.058,-14.209 r1.024
  circle w0.254: c13.598,-14.184 r1.024
  circle w0.254: c16.138,-14.184 r1.024
Mechanical 15:
  lines w0.025: 6.319,-3.611 6.319,-2.811 7.719,-2.811 ; 12.669,-11.574 12.669,-12.374 14.069,-12.374 14.069,-11.574
  lines w0.1: 4.733,5.984 5.19,5.984 5.47,5.984 ; 4.733,6.568 5.19,6.568 5.495,6.568 ; 13.242,-12.203 13.242,-11.746 ; 13.521,-12.203 13.521,-11.746 ; 15.274,-12.228 15.274,-11.771 15.274,-11.466 ; 15.858,-12.228 15.858,-11.771 15.858,-11.492
3D body "RM254_3pin.STEP": height 6.02, standoff -3.1, extent 9.94,-15.5 17.56,-12.96
3D body "RM254_3pin.STEP": height 6.02, standoff -3.1, extent 9.63,11 17.25,13.54
3D body: height 7, standoff 6, extent -14.2,-18.2 18.1,16.3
